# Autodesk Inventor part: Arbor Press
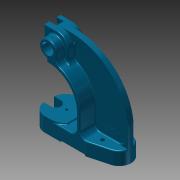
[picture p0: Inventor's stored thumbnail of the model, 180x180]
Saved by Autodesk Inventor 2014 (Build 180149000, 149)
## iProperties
Shininess: 64.0
Length Units: 11272
Angle Units: 11279
Time Units: 11290
Mass Units: 11286
Length Display Precision: 3
Angle Display Precision: 2
Compacted: True
Part Number: Arbor Press
Document SubType Name: Modeling
Created: 2003-11
Designer: Autodesk, Inc.
Manufacturer: Standard
Standards Organization: Custom
Mass: 6013.13 g
Surface Area: 1633.45 cm^2
Volume: 766.003 cm^3
Density: 7.85 g/cm^3
Material: Cast Steel
Appearance: Sky Blue Dark
Density: 0.0
Volumn: 0.0
Area: 0.0
PropertySet Name: Model Information
Control State: 0
Master: False
Checked Out: False
Title: Arbor Press
Author: Autodesk, Inc.
Revision Number: A
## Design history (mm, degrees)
sketch "Sketch7"
  geometry: L1 (0, 0)-(0, 38.1); L2 (0, 38.1)-(79.375, 38.1); L3 (79.375, 38.1)-(79.375, 34.925); L4 (79.375, 34.925)-(117.475, 34.925); L5 (41.275, 165.1)-(11.201, 165.1); L6 (11.201, 165.1)-(11.201, 228.6); L7 (11.201, 228.6)-(66.675, 228.6); L8 (219.075, 76.2)-(219.075, 0); L9 (219.075, 0)-(141.275, 0); L10 (141.275, 0)-(0, 0); L11 (117.475, 34.925)-(117.475, 88.9); A1 r 152.4 centre (66.675, 76.2) between (219.075, 76.2) and (66.675, 228.6); A2 r 76.2 centre (41.275, 88.9) between (117.475, 88.9) and (41.275, 165.1)
  constraints: 22 end point, 8 parallel, 4 point on circle, 4 tangent, 2 centre point, 2 perpendicular, 1 collinear, 1 vertical
  dimensions: "d46" = 79.375 distance of L1.end L2.end; "d47" = 38.1 distance of L1.start L1.end; "d52" = 219.075 distance between parallel lines of L8 L1; "d53" = 228.6 distance between parallel lines of L10 L7; "d54" = 3.175 distance between parallel lines of L4 L2; "d55" = 152.4 radius of A1; "d56" = 76.2 radius of A2; "d57" = 63.5 distance of L5.end L6.end; "d59" = 25.4 horizontal distance of A1.centre A2.centre; "d60" = 30.0736 horizontal distance of A2.centre L5.end
extrude "Extrusion6" new body sketch "Sketch7" distance "d61" = 88.9; taper "d62" = 0 deg
sketch "Sketch8"
  geometry: L1 (207.874, 0)-(55.474, 0) reference; L2 (0, 0)-(55.474, 0) reference; L3 (-11.201, 0)-(68.174, 0) reference; L4 (-11.201, 0)-(-11.201, -88.9) reference; L5 (-11.201, -88.9)-(68.174, -88.9) reference; L6 (207.874, -88.9)-(55.474, -88.9) reference; L7 (207.874, 0)-(207.874, -88.9) reference; L8 (-11.201, -44.45)-(207.874, -44.45); L9 (-11.201, -44.45)-(-11.201, -33.325); L10 (22.123, 0)-(132.907, 0); L11 (132.907, 0)-(184.341, -13.782); L12 (22.123, -88.9)-(132.907, -88.9); L13 (132.907, -88.9)-(184.341, -75.118); L14 (-11.201, -44.45)-(-11.201, -55.575); A1 r 33.325 centre (22.123, -33.325) between (22.123, 0) and (-11.201, -33.325); A2 r 31.75 centre (176.124, -44.45) between (207.874, -44.45) and (184.341, -13.782); A3 r 33.325 centre (22.123, -55.575) between (-11.201, -55.575) and (22.123, -88.9); A4 r 31.75 centre (176.124, -44.45) between (184.341, -75.118) and (207.874, -44.45)
  constraints: 14 end point, 8 point on circle, 5 symmetric about line, 4 centre point, 4 point on line, 4 tangent, 2 midpoint, 1 collinear, 4 other
  dimensions: "d63" = 15 deg angle of L1 L11; "d64" = 33.3248 radius of A1; "d65" = 31.75 radius of A2
extrude "Extrusion7" sketch "Sketch8" stored distance "d66" = 88.9; taper "d67" = 0 deg
sketch "Sketch9"
  geometry: L1 (141.275, 3.175)-(76.2, 3.175) reference; L2 (144.108, 0)-(195.543, 0) reference; L3 (79.375, 34.925)-(117.475, 34.925) reference; L4 (117.475, 34.925)-(117.475, 88.9) reference; L5 (219.075, 34.925)-(127, 34.925); L6 (219.075, 76.2)-(219.075, 0) reference; L7 (11.201, 228.6)-(11.201, 165.1) reference; L8 (219.075, 34.925)-(219.075, 76.2); L9 (127, 88.9)-(127, 34.925); L10 (73.025, 228.6)-(73.025, 168.529); L11 (33.325, 228.6)-(66.675, 228.6) reference; A1 r 76.2 centre (41.275, 88.9) between (117.475, 88.9) and (41.275, 165.1) reference; A2 r 152.4 centre (66.675, 76.2) between (144.108, 207.463) and (66.675, 228.6) reference; A3 r 152.4 centre (66.675, 76.2) between (195.543, 157.557) and (144.108, 207.463) reference; A4 r 152.401 centre (66.674, 76.2) between (219.075, 76.2) and (195.543, 157.557); A5 r 152.4 centre (66.675, 76.2) between (195.543, 157.557) and (144.108, 207.463); A6 r 85.725 centre (41.275, 88.9) between (127, 88.9) and (73.025, 168.529); A7 r 152.4 centre (66.675, 76.2) between (144.108, 207.463) and (73.025, 228.468)
  constraints: 8 end point, 8 point on circle, 4 centre point, 3 concentric, 2 point on line, 1 collinear
  dimensions: "d86" = 9.525 distance between parallel lines of L9 L4; "d87" = 61.8236 distance between parallel lines of L10 L7; "d88" = 85.725 radius of A6; "d89" = 152.40105 radius of A4
workplane "Work Plane2"
extrude "Extrusion9" cut sketch "Sketch9" distance "d90" = 37.3126; taper "d91" = 0 deg
sketch "Sketch12"
  geometry: L1 (127, 34.925)-(127, 88.9) reference; L2 (144.108, 34.925)-(127, 34.925) reference; L3 (195.543, 34.925)-(144.108, 34.925) reference; L4 (195.543, 34.925)-(218.262, 34.925) reference; L5 (127, 88.9)-(127, 34.925); L6 (218.262, 91.917)-(218.262, 34.925) reference; L7 (208.737, 91.417)-(208.737, 34.925); L8 (66.212, 219.075)-(66.675, 219.075); L9 (208.737, 34.925)-(127, 34.925); L10 (41.275, 228.6)-(73.025, 168.529) reference; L11 (73.025, 168.529)-(73.025, 218.934); L12 (73.025, 228.468)-(73.025, 228.6); A1 r 85.725 centre (41.275, 88.9) between (127, 88.9) and (73.025, 168.529) reference; A2 r 85.725 centre (41.275, 88.9) between (127, 88.9) and (73.025, 168.529); A3 r 152.4 centre (66.675, 76.2) between (195.543, 157.557) and (66.675, 228.6) reference; A4 r 152.401 centre (66.674, 76.2) between (218.262, 91.917) and (195.543, 157.557) reference; A5 r 142.875 centre (66.675, 76.2) between (187.488, 152.472) and (73.025, 218.934); A6 r 142.876 centre (66.674, 76.2) between (208.737, 91.417) and (187.488, 152.472); A7 r 85.725 centre (41.275, 88.9) between (127, 88.9) and (73.025, 168.529) reference; 1 further point
  constraints: 12 end point, 9 point on circle, 3 centre point, 2 tangent, 1 collinear, 1 concentric, 1 point on line
  dimensions: "d93" = 9.525 radial gap between concentric circles of A3 A5; "d94" = 9.525 distance between parallel lines of L6 L7; "d99" = 0 distance between parallel lines of L10 L11; "d100" = 9.525 radial gap between concentric circles of A4 A6
extrude "Extrusion10" cut sketch "Sketch12" distance "d96" = 3.175; taper "d97" = 0 deg
sketch "Sketch13"
  geometry: L1 (33.325, 165.1)-(11.201, 165.1) reference; L2 (11.201, 228.6)-(11.201, 165.1) reference; L3 (11.201, 228.6)-(33.325, 228.6) reference; L4 (33.325, 228.6)-(66.675, 228.6) reference; L5 (41.275, 165.1)-(33.325, 165.1) reference; L6 (38.1, 165.1)-(38.1, 174.853); L7 (11.201, 196.85)-(77.125, 196.85); L8 (63.5, 196.85)-(63.5, 171.694); L9 (73.025, 168.529)-(73.025, 228.468) reference; L10 (38.1, 165.1)-(11.201, 165.1); L11 (11.201, 165.1)-(11.201, 228.6); L12 (73.025, 228.468)-(73.025, 168.529); L13 (12.066, 228.6)-(66.675, 228.6); A1 r 76.2 centre (41.275, 88.9) between (117.475, 88.9) and (41.275, 165.1) reference; A2 r 152.4 centre (66.675, 76.2) between (73.025, 228.468) and (66.675, 228.6) reference; A3 r 22.225 centre (41.275, 196.85) between (63.5, 196.85) and (38.1, 174.853); A4 r 85.725 centre (41.275, 88.9) between (127, 88.9) and (73.025, 168.529) reference; A5 r 85.725 centre (41.275, 88.9) between (73.025, 168.529) and (63.5, 171.694); A6 r 152.4 centre (66.675, 76.2) between (73.025, 228.468) and (66.675, 228.6)
  constraints: 14 end point, 6 point on circle, 4 perpendicular, 4 point on line, 3 centre point, 3 collinear, 2 concentric, 2 tangent, 1 midpoint
  dimensions: "d101" = 44.45 diameter of A3; "d102" = 30.0736 distance from line of L2 A3.centre; "d103" = 3.175 distance from line of A3.centre L6; "d105" = 9.525 radial gap between concentric circles of A1 A5
extrude "Extrusion11" cut sketch "Sketch13" distance "d106" = 22.225; taper "d107" = 0 deg
mirror "Mirror3"
sketch "Sketch14"
  geometry: L1 (0, 63.5)-(58.272, 63.5) reference; L2 (-8.403, 63.5)-(0, 63.5) reference; L3 (-8.403, 63.5)-(-8.403, 0) reference; L4 (0, 0)-(58.272, 0) reference; L5 (58.272, 0)-(58.272, 63.5) reference; L6 (58.272, 53.975)-(80.497, 53.975) reference; L7 (80.497, 52.504)-(80.497, 10.996) reference; L8 (80.497, 31.75)-(80.497, 53.975) reference; L9 (80.497, 9.753)-(80.497, 0) reference; L10 (80.497, 9.753)-(80.497, 10.996) reference; L11 (80.497, 0)-(58.272, 0) reference; L12 (13.822, 63.5)-(13.822, 9.525); L13 (13.822, 63.5)-(-8.403, 63.5); L14 (-8.403, 63.5)-(-8.403, 9.525); L15 (-8.403, 9.525)-(13.822, 9.525); L16 (0, 0)-(-8.403, 0) reference
  constraints: 8 end point, 3 perpendicular, 1 point on line
  dimensions: "d109" = 44.45 distance between parallel lines of L5 L12; "d111" = 9.525 distance between parallel lines of L4 L15
extrude "Extrusion12" cut sketch "Sketch14" stored distance "d112" = 22.225; taper "d113" = 0 deg
sketch "Sketch16"
  geometry: L1 (-33.325, 174.625)-(-73.025, 174.625) reference; L2 (-33.325, 174.625)-(-33.325, 165.1) reference; L3 (-73.025, 174.625)-(-73.025, 168.529) reference; L4 (-73.025, 168.529)-(-73.025, 174.625); L5 (-73.025, 174.625)-(-41.275, 174.625); A1 r 85.725 centre (-41.275, 88.9) between (-73.025, 168.529) and (-127, 88.9) reference; A2 r 85.725 centre (-41.275, 88.9) between (-41.275, 174.625) and (-73.025, 168.529)
  constraints: 4 end point, 2 collinear, 2 point on circle, 2 tangent, 1 centre point, 1 concentric, 1 point on line
extrude "Extrusion13" cut sketch "Sketch16" distance "d116" = 22.225; taper "d117" = 0 deg
workplane "Work Plane5"
sketch "Sketch17"
  geometry: L1 (11.201, 228.6)-(11.201, 174.625) reference; L2 (66.675, 228.6)-(11.201, 228.6) reference; L3 (73.025, 168.529)-(73.025, 228.468) reference; L4 (11.201, 215.9)-(41.275, 215.9); L5 (41.275, 177.8)-(11.201, 177.8); L6 (33.325, 165.1)-(11.201, 165.1) reference; A1 r 152.4 centre (66.675, 76.2) between (73.025, 228.468) and (66.675, 228.6) reference; A2 r 19.05 centre (41.275, 196.85) between (41.275, 177.8) and (41.275, 215.9)
  constraints: 4 end point, 2 point on circle, 2 point on line, 1 centre point, 1 parallel, 1 tangent
  dimensions: "d120" = 38.1 distance between parallel lines of L5 L4; "d121" = 19.05 radius of A2; "d122" = 12.7 distance of L1.start L4.start; "d123" = 12.7 distance of L6.end L5.end; "d124" = 30.0736 distance from line of L1 A2.centre
extrude "Extrusion14" cut sketch "Sketch17" stored distance "d125" = 25.4; taper "d126" = 0 deg
sketch "Sketch18"
  geometry: C1 r 14.879 at (41.275, 196.85); A1 r 22.225 centre (41.275, 196.85) between (63.5, 196.85) and (33.325, 217.604) reference
  constraints: 1 centre point, 1 coincident
  dimensions: "d127" = 29.758 diameter of C1
extrude "Extrusion15" cut sketch "Sketch18" distance "d128" = 38.1; taper "d129" = 0 deg
sketch "Sketch19"
  geometry: C1 r 9.538 at (41.275, 196.85); A1 r 22.225 centre (41.275, 196.85) between (63.5, 196.85) and (33.325, 217.604) reference; 2 further points
  constraints: 1 centre point, 1 coincident
  dimensions: "d130" = 19.0754 diameter of C1
extrude "Extrusion16" cut sketch "Sketch19" distance "d131" = 25.4; taper "d132" = 0 deg
fillet "Fillet2" dims "d134" = 15.875
fillet "Fillet3" dims "d135" = 15.875
sketch "Sketch20"
  geometry: L1 (11.201, 228.6)-(66.675, 228.6) reference; L2 (73.025, 228.468)-(73.025, 178.646) reference; L3 (41.275, 228.6)-(66.675, 228.6); L4 (73.025, 228.468)-(73.025, 196.85); C1 r 9.538 at (41.275, 196.85) reference; A1 r 31.75 centre (41.275, 196.85) between (73.025, 196.85) and (41.275, 228.6); A2 r 152.4 centre (66.675, 76.2) between (73.025, 228.468) and (66.675, 228.6) reference; A3 r 152.4 centre (66.675, 76.2) between (73.025, 228.468) and (66.675, 228.6)
  constraints: 4 end point, 4 point on circle, 2 centre point, 2 point on line, 2 tangent, 1 coincident, 1 collinear, 1 concentric
extrude "Extrusion17" cut sketch "Sketch20" distance "d136" = 15.0876; taper "d137" = 0 deg
mirror "Mirror4"
fillet "Fillet4" dims "d138" = 15.875
fillet "Fillet5" dims "d139" = 3.175
fillet "Fillet6" dims "d140" = 3.175
fillet "Fillet7" dims "d141" = 15.875
sketch "Sketch22"
  geometry: L1 (-79.375, 55.575)-(-79.375, 33.325) reference; L2 (-46.05, 0)-(0, 0) reference; L3 (-46.05, 88.9)-(0, 88.9) reference; L4 (-79.375, 44.45)-(-18.816, 44.45); L5 (-60.325, 57.944)-(-79.375, 57.944); L6 (-79.375, 30.956)-(-60.325, 30.956); L7 (-79.375, 57.944)-(-79.375, 30.956); A1 r 33.325 centre (-46.05, 55.575) between (-46.05, 88.9) and (-79.375, 55.575) reference; A2 r 33.325 centre (-46.05, 33.325) between (-79.375, 33.325) and (-46.05, 0) reference; A3 r 13.494 centre (-60.325, 44.45) between (-60.325, 30.956) and (-60.325, 57.944)
  constraints: 8 end point, 3 perpendicular, 3 point on line, 2 point on circle, 2 tangent, 1 centre point, 1 midpoint, 1 parallel
  dimensions: "d147" = 26.9875 diameter of A3; "d148" = 19.05 distance of L4.start A3.centre
extrude "Extrusion19" cut sketch "Sketch22" stored distance "d149" = 3.175; taper "d150" = 0 deg
sketch "Sketch23"
  geometry: L1 (0, 88.9)-(0, 0) reference; L2 (-46.05, 0)-(0, 0) reference; L3 (-60.325, 44.45)-(-10.181, 44.45); L4 (0, 13.341)-(0, 0); L5 (0, 0)-(-31.75, 0); A1 r 44.45 centre (-31.75, 44.45) between (-31.75, 0) and (0, 13.341); A2 r 13.494 centre (-60.325, 44.45) between (-60.325, 30.956) and (-60.325, 57.944) reference
  constraints: 6 end point, 3 point on line, 2 point on circle, 1 centre point, 1 parallel, 1 perpendicular
  dimensions: "d151" = 88.9 diameter of A1; "d153" = 28.575 distance of A1.centre L3.start
extrude "Extrusion20" cut sketch "Sketch23" distance "d154" = 3.175; taper "d155" = 0 deg
mirror "Mirror5"
fillet "Fillet10" dims "d157" = 15.875
fillet "Fillet11" dims "d158" = 15.875
fillet "Fillet12" dims "d159" = 15.875
fillet "Fillet15" dims "d162" = 15.875
sketch "Sketch24"
  geometry: L1 (-33.241, 57.944)-(-14.275, 57.944) reference; L2 (-14.275, 30.956)-(-33.241, 30.956) reference; L3 (110.783, 0)-(0, 0) reference; L4 (162.218, 13.782)-(110.783, 0) reference; L5 (110.783, 88.9)-(162.218, 75.118) reference; L6 (110.783, 88.9)-(0, 88.9) reference; L7 (0, 80.975)-(109.74, 80.975); L8 (109.74, 80.975)-(160.167, 67.463); L9 (160.167, 21.437)-(109.74, 7.925); L10 (109.74, 7.925)-(0, 7.925); L11 (-23.221, 23.031)-(-14.275, 23.031); L12 (-14.275, 65.869)-(-23.221, 65.869); A1 r 13.494 centre (-14.275, 44.45) between (-14.275, 30.956) and (-14.275, 57.944) reference; A2 r 33.325 centre (0, 33.325) between (-33.241, 30.956) and (0, 0) reference; A3 r 31.75 centre (154, 44.45) between (162.218, 13.782) and (162.218, 75.118) reference; A4 r 33.325 centre (0, 55.575) between (0, 88.9) and (-33.241, 57.944) reference; A5 r 23.825 centre (154, 44.45) between (160.167, 21.437) and (160.167, 67.463); A6 r 25.4 centre (0, 33.325) between (-23.221, 23.031) and (0, 7.925); A7 r 21.419 centre (-14.275, 44.45) between (-14.275, 23.031) and (-14.275, 65.869); A8 r 25.4 centre (0, 55.575) between (0, 80.975) and (-23.221, 65.869)
  constraints: 12 end point, 8 point on circle, 4 centre point, 9 other
  dimensions: "d163" = 7.9248 distance between parallel lines of L7 L6
extrude "Extrusion21" cut sketch "Sketch24" distance "d164" = 26.9875; taper "d165" = 0 deg
sketch "Sketch25"
  geometry: L1 (144.108, 0)-(33.325, 0) reference; L2 (33.325, 0)-(0.084, 0) reference; L3 (0.084, 38.1)-(0.084, 0) reference; L4 (76.284, 0)-(76.284, 3.175); L5 (76.284, 3.175)-(141.359, 3.175); L6 (141.359, 3.175)-(141.359, 0)
  constraints: 6 end point, 2 parallel, 2 point on line, 1 perpendicular
  dimensions: "d166" = 76.2 distance between parallel lines of L3 L4; "d167" = 65.0748 distance of L4.end L5.end; "d168" = 3.175 distance between parallel lines of L1 L5
extrude "Extrusion22" cut sketch "Sketch25" stored distance "d169" = 26.9875; taper "d170" = 0 deg
sketch "Sketch27"
  geometry: L1 (-23.221, 65.869)-(-14.275, 65.869) reference; L2 (-14.275, 23.031)-(-23.221, 23.031) reference; L3 (0, 7.925)-(109.74, 7.925) reference; L4 (109.74, 7.925)-(160.167, 21.437) reference; L5 (160.167, 67.463)-(109.74, 80.975) reference; L6 (109.74, 80.975)-(0, 80.975) reference; L7 (27, 80.975)-(27, 7.925); L8 (103.226, 80.975)-(103.226, 7.925); L9 (27, 80.975)-(103.226, 80.975); L10 (27, 7.925)-(103.226, 7.925); A1 r 25.4 centre (0, 55.575) between (0, 80.975) and (-23.221, 65.869) reference; A2 r 21.419 centre (-14.275, 44.45) between (-14.275, 23.031) and (-14.275, 65.869) reference; A3 r 25.4 centre (0, 33.325) between (-23.221, 23.031) and (0, 7.925) reference; A4 r 23.825 centre (154, 44.45) between (160.167, 21.437) and (160.167, 67.463) reference; A5 r 31.75 centre (154, 44.45) between (162.218, 13.782) and (162.218, 75.118) reference; 1 further point
  constraints: 8 end point, 4 point on line, 2 collinear, 2 perpendicular
  dimensions: "d176" = 60.325 distance from line of L7 point (-33.325, 0); "d178" = 50.7746 distance from line of A4.centre L8
extrude "Extrusion23" join sketch "Sketch27" distance "d179" = 12.6873; taper "d180" = 0 deg
workplane "Work Plane7"
sketch "Sketch28"
  geometry: L1 (-136.55, 14.3)-(-136.55, 26.988) reference; L2 (-60.325, 14.3)-(-136.55, 14.3) reference; L3 (-136.55, 26.988)-(-114.575, 14.3); L4 (-114.575, 14.3)-(-136.55, 14.3); L5 (-136.55, 14.3)-(-136.55, 26.988)
  constraints: 6 end point, 1 collinear, 1 perpendicular, 1 point on line
  dimensions: "d182" = 30 deg angle of L2 L3
extrude "Extrusion24" cut sketch "Sketch28" stored distance "d183" = 73.0504; taper "d184" = 0 deg
fillet "Fillet17" dims "d185" = 3.175
sketch "Sketch29"
  geometry: L1 (-58.272, 0)-(0, 0) reference; L2 (0, 0)-(0, 63.5) reference; L3 (-44.45, 63.5)-(0, 63.5) reference; L4 (-44.45, 63.5)-(-44.45, 9.525) reference; L5 (-58.272, 0)-(-58.272, 9.525) reference; L6 (-9.525, 50.8)-(-9.525, 12.7) reference; L7 (-9.525, 12.7)-(-34.925, 12.7) reference; L8 (-34.925, 12.7)-(-34.925, 50.8) reference; L9 (-34.925, 50.8)-(-9.525, 50.8) reference; L10 (-22.225, 63.5)-(-22.225, 0); L11 (-6.35, 57.15)-(-61.925, 57.15); L12 (-34.925, 31.75)-(-9.525, 31.75); L13 (-44.45, 9.525)-(-58.272, 9.525) reference; 3 further points
  constraints: 6 end point, 3 midpoint, 2 perpendicular, 2 point on line, 2 symmetric about line
  dimensions: "d186" = 31.75 distance of L11.start point (-38.1, 57.15); "d187" = 15.875 distance from line of L11.start L10; "d188" = 6.35 distance from line of L3 L11.start
hole "Hole1" sketch "Sketch29" at (-38.1, 57.15), (-6.35, 57.15), (-38.1, 6.35), (-6.35, 6.35) diameter "d189" = 4.9784; stored, may be unused: countersink angle "d193" = 82 deg, drill point angle "d195" = 118 deg; dims "d190" = 12.7, "d191" = 9.525, "d192" = 6.35, "d194" = 19.1008
sketch "Sketch30"
  geometry: L1 (-31.75, -49.954)-(-31.75, -31.75) reference; L2 (30.074, -53.975)-(0, -53.975) reference; L3 (30.074, 0)-(30.074, -53.975) reference; L4 (0, 0)-(30.074, 0) reference; L5 (20.549, -19.05)-(20.549, -44.45); L6 (30.074, -63.5)-(7.95, -63.5) reference; C1 r 9.538 at (0, -31.75) reference; A1 r 31.75 centre (0, -31.75) between (0, 0) and (-31.75, -31.75) reference; A2 r 15.875 centre (-47.625, -49.954) between (-40.184, -63.976) and (-31.75, -49.954) reference; A3 r 85.725 centre (0, -139.7) between (0, -53.975) and (-40.184, -63.976) reference; 1 further point
  constraints: 2 end point
  dimensions: "d196" = 25.4 distance of L5.start L5.end; "d197" = 9.525 distance from line of L3 L5.start; "d255" = 6.35 vertical distance of point (30.074, -50.8) L5.end; "d256" = 20.5486 horizontal distance of A1.centre L5.end
hole "Hole2" sketch "Sketch30" at (20.549, -19.05), (20.549, -44.45) diameter "d199" = 3.9624; stored, may be unused: countersink angle "d203" = 82 deg, drill point angle "d205" = 118 deg; dims "d200" = 12.7, "d201" = 9.525, "d202" = 6.35, "d204" = 19.05
sketch "Sketch31"
  geometry: C1 r 9.538 at (0, -31.75) reference; C2 r 17.45 at (0, -31.75)
  constraints: 1 centre point, 1 coincident
  dimensions: "d206" = 17.4498 radius of C2
extrude "Extrusion25" join sketch "Sketch31" distance "d207" = 9.525; taper "d208" = 0 deg
fillet "Fillet19" dims "d210" = 3.175
sketch "Sketch32"
  geometry: L1 (-42.85, 29.362)-(-42.85, 38.887) reference; L2 (-25.4, 38.887)-(-25.4, 5.475); L3 (-42.85, 38.887)-(-7.95, 38.887) reference; 1 further point
  constraints: 2 end point, 1 parallel, 1 point on line
  dimensions: "d290" = 4.7625 distance from line of L3 point (-25.4, 34.125)
hole "Hole3" sketch "Sketch32" at (-25.4, 34.125) diameter "d212" = 3.175; stored, may be unused: countersink angle "d216" = 82 deg, drill point angle "d218" = 118 deg; dims "d213" = 12.7, "d214" = 9.525, "d215" = 6.35, "d217" = 25.4
sketch "Sketch34"
  geometry: A1 r 13.494 centre (-173.812, 7.137) between (-173.812, -6.356) and (-173.812, 20.631) reference; 1 further point
  dimensions: "d228" = 142.875 horizontal distance of point (-30.937, -11.913) A1.centre; "d229" = 19.05 vertical distance of point (-30.937, -11.913) A1.centre
hole "Hole5" sketch "Sketch34" at (-30.937, -11.913) diameter "d230" = 10.3124; stored, may be unused: countersink angle "d234" = 82 deg, drill point angle "d236" = 118 deg; dims "d231" = 12.7, "d232" = 9.525, "d233" = 6.35, "d235" = 12.7
mirror "Mirror6"
sketch "Sketch35"
  geometry: A1 r 13.494 centre (18.966, -13.494) between (18.966, -26.988) and (18.966, 0) reference; 1 further point
  dimensions: "d237" = 28.575 distance of point (47.541, -13.494) A1.centre; "d238" = 0 vertical distance of A1.centre point (47.541, -13.494)
hole "Hole6" sketch "Sketch35" at (47.541, -13.494) diameter "d239" = 6.731; stored, may be unused: countersink angle "d243" = 82 deg, drill point angle "d245" = 118 deg; dims "d240" = 12.7, "d241" = 9.525, "d242" = 6.35, "d244" = 12.7
sketch "Sketch36"
  geometry: L1 (-58.272, 0)-(0, 0) reference; L2 (0, 0)-(0, 63.5) reference; L3 (-44.45, 63.5)-(0, 63.5) reference; L4 (-44.45, 63.5)-(-44.45, 9.525) reference; L5 (-58.272, 0)-(-58.272, 9.525) reference; L6 (-9.525, 50.8)-(-9.525, 12.7) reference; L7 (-9.525, 12.7)-(-34.925, 12.7) reference; L8 (-34.925, 12.7)-(-34.925, 50.8) reference; L9 (-34.925, 50.8)-(-9.525, 50.8) reference; L10 (-31.75, 63.5)-(-31.75, 50.8); L11 (-12.725, 63.5)-(-12.725, 50.8); L12 (-34.925, 31.75)-(-9.525, 31.75); L13 (-22.225, 50.8)-(-22.225, 31.75); L14 (-31.75, 63.5)-(-12.725, 63.5); L15 (-31.75, 50.8)-(-12.725, 50.8); L16 (-44.45, 9.525)-(-58.272, 9.525) reference; C1 r 2.489 at (-38.1, 6.35) reference; C2 r 2.489 at (-38.1, 57.15) reference; C3 r 2.489 at (-6.35, 57.15) reference; C4 r 2.489 at (-6.35, 6.35) reference
  constraints: 12 end point, 4 midpoint, 4 point on line, 3 perpendicular, 1 parallel
  dimensions: "d246" = 19.0246 distance between parallel lines of L11 L10; "d247" = 9.4996 distance between parallel lines of L11 L13
extrude "Extrusion26" cut sketch "Sketch36" distance "d248" = 19.1008; taper "d249" = 0 deg
workplane "Work Plane8"
mirror "Mirror7"
sketch "Sketch37"
  geometry: L1 (-11.201, 174.625)-(-41.275, 174.625) reference; L2 (-30.302, 165.1)-(-11.201, 165.1) reference; L3 (-11.201, 165.1)-(-11.201, 177.8) reference; L4 (-11.201, 174.625)-(-11.201, 165.1); L5 (-41.275, 174.625)-(-11.201, 174.625); L6 (-41.275, 174.625)-(-41.275, 165.1); L7 (-11.201, 165.1)-(-41.275, 165.1)
  constraints: 8 end point, 2 collinear, 2 perpendicular
extrude "Extrusion27" join sketch "Sketch37" distance "d251" = 12.7; taper "d252" = 0 deg
delete_face "Delete Face1"
sketch "Sketch39"
  geometry: L1 (180.803, 172.743)-(244.935, 172.743); L2 (244.935, 172.743)-(244.935, 72.014); L3 (244.935, 72.014)-(180.803, 72.014); L4 (180.803, 72.014)-(180.803, 172.743)
  constraints: 8 end point, 2 parallel, 1 horizontal, 1 perpendicular
extrude "Extrusion28" cut sketch "Sketch39" distance "d264" = 25.4; taper "d265" = 0 deg
mirror "Mirror8"
fillet "Fillet21" dims "d266" = 3.175
fillet "Fillet22" dims "d267" = 3.175
fillet "Fillet23" dims "d268" = 3.175
sketch "Sketch40"
  geometry: L1 (-3.175, -34.138)-(-30.956, -34.138) reference; L2 (-3.175, -34.138)-(-3.175, -18.263) reference; L3 (-30.956, -18.263)-(-3.175, -18.263) reference; L4 (-30.956, -34.138)-(-30.956, -18.263) reference; L5 (-47.625, -18.263)-(-47.625, -34.138) reference; L6 (-23.812, 34.125)-(-23.812, -34.138); L7 (-6.35, -37.313)-(-44.45, -37.313) reference; C1 r 1.587 at (-23.812, -26.213); 2 further points
  constraints: 2 end point, 2 point on line, 1 centre point, 1 perpendicular
  dimensions: "d272" = 3.175 diameter of C1; "d275" = 11.0998 distance from line of L7 C1.centre
extrude "Extrusion29" cut sketch "Sketch40" distance "d276" = 25.4; taper "d277" = 0 deg
sketch "Sketch41"
  geometry: L1 (22.225, 60.325)-(22.225, 9.525) reference; L2 (22.225, 9.525)-(0, 9.525) reference; L3 (0, 0)-(0, 9.525) reference; L4 (0, 0)-(34.925, 0) reference; L5 (34.925, 0)-(34.925, 12.7) reference; L6 (31.75, 12.7)-(31.75, 50.8) reference; L7 (34.925, 50.8)-(34.925, 63.5) reference; L8 (25.4, 63.5)-(34.925, 63.5) reference; L9 (22.225, 9.525)-(22.225, 0); L10 (22.225, 0)-(0, 0); L11 (0, 0)-(0, 9.525); L12 (0, 9.525)-(22.225, 9.525); L13 (34.925, 12.7)-(31.75, 12.7) reference; L14 (31.75, 50.8)-(34.925, 50.8) reference; C1 r 2.489 at (28.575, 57.15) reference; C2 r 2.489 at (28.575, 6.35) reference; A1 r 3.175 centre (25.4, 60.325) between (25.4, 63.5) and (22.225, 60.325) reference
  constraints: 8 end point, 2 collinear, 2 perpendicular, 1 point on line
extrude "Extrusion30" cut sketch "Sketch41" distance "d278" = 26.8986; taper "d279" = 0 deg
fillet "Fillet27" dims "d280" = 3.175
fillet "Fillet28" dims "d281" = 3.175
fillet "Fillet30" dims "d283" = 3.175
sketch "Sketch42"
  geometry: L1 (3.175, -31.75)-(3.175, -22.225) reference; L2 (-102.833, -196.85)-(-102.833, -165.1) reference; L3 (-102.833, -196.85)-(-100.084, -196.85) reference; L4 (-100.084, -193.675)-(-35.009, -193.675) reference; L5 (7.95, -158.75)-(7.95, -196.85) reference; L6 (7.95, -158.75)-(-6.35, -158.75) reference; L7 (3.175, -22.225)-(3.175, -17.159); L8 (-17.45, 0)-(-17.45, -24.02); L9 (0, -22.225)-(3.175, -22.225); L10 (-102.833, -165.1)-(-101.6, -165.1) reference; L11 (-82.55, -146.05)-(-82.55, -107.95) reference; L12 (-60.325, -165.1)-(-6.35, -165.1) reference; L13 (-79.375, -107.95)-(-79.375, -146.05) reference; L14 (3.175, -28.575)-(0, -28.575) reference; L15 (3.175, -28.575)-(3.175, -25.4) reference; L16 (0, -25.4)-(3.175, -25.4) reference; L17 (-100.084, -196.85)-(-100.084, -193.675) reference; L18 (-35.009, -193.675)-(-35.009, -196.85) reference; L19 (-35.009, -196.85)-(7.95, -196.85) reference; L20 (-6.35, -158.75)-(-6.35, -165.1) reference; A1 r 17.45 centre (0, 0) between (3.175, -17.159) and (-17.45, 0) reference; A2 r 17.45 centre (0, 0) between (-17.45, 0) and (3.175, -17.159); A3 r 85.725 centre (0, -107.95) between (0, -22.225) and (-17.45, -24.02); A4 r 82.55 centre (0, -107.95) between (0, -25.4) and (-82.55, -107.95) reference; A5 r 19.05 centre (-101.6, -146.05) between (-101.6, -165.1) and (-82.55, -146.05) reference; A6 r 19.05 centre (-60.325, -146.05) between (-79.375, -146.05) and (-60.325, -165.1) reference; A7 r 79.375 centre (0, -107.95) between (0, -28.575) and (-79.375, -107.95) reference
  constraints: 6 end point, 6 point on circle, 3 tangent, 2 centre point, 1 concentric, 1 parallel, 1 perpendicular
extrude "Extrusion31" join sketch "Sketch42" distance "d284" = 9.525; taper "d285" = 0 deg
fillet "Fillet31" dims "d286" = 3.175
fillet "Fillet32" dims "d287" = 3.175
fillet "Fillet33" dims "d288" = 3.175
fillet "Fillet34" dims "d289" = 3.175
sketch "Sketch43"
  geometry: L1 (123.521, 60.955)-(212.511, 60.955); L2 (212.511, 60.955)-(212.511, 48.209); L3 (212.511, 48.209)-(123.521, 48.209); L4 (123.521, 48.209)-(123.521, 60.955)
  constraints: 2 other
emboss "Emboss1" sketch "Sketch43" dims "d293" = 2.54, "d294" = 0
fillet "Fillet35" dims "d295" = 3.175
fillet "Fillet36" dims "d296" = 3.175
fillet "Fillet37" dims "d297" = 3.175
fillet "Fillet38" dims "d298" = 3.175
fillet "Fillet39" dims "d299" = 3.175
body "Solid1"
node "Projected Loop4"
node "Projected Loop5"
node "Projected Loop6"
node "Projected Loop7"
node "Projected Loop8"
node "Projected Loop9"
node "Projected Loop10"
node "Projected Loop11"
other parameters: "d32" = 47.625, "d33" = 47.625, "d39" = 47.625, "d76" = 61.8236, "d80" = -44.45, "d98" = 31.75, "d118" = -22.225, "d181" = -44.45, "d250" = -31.75
